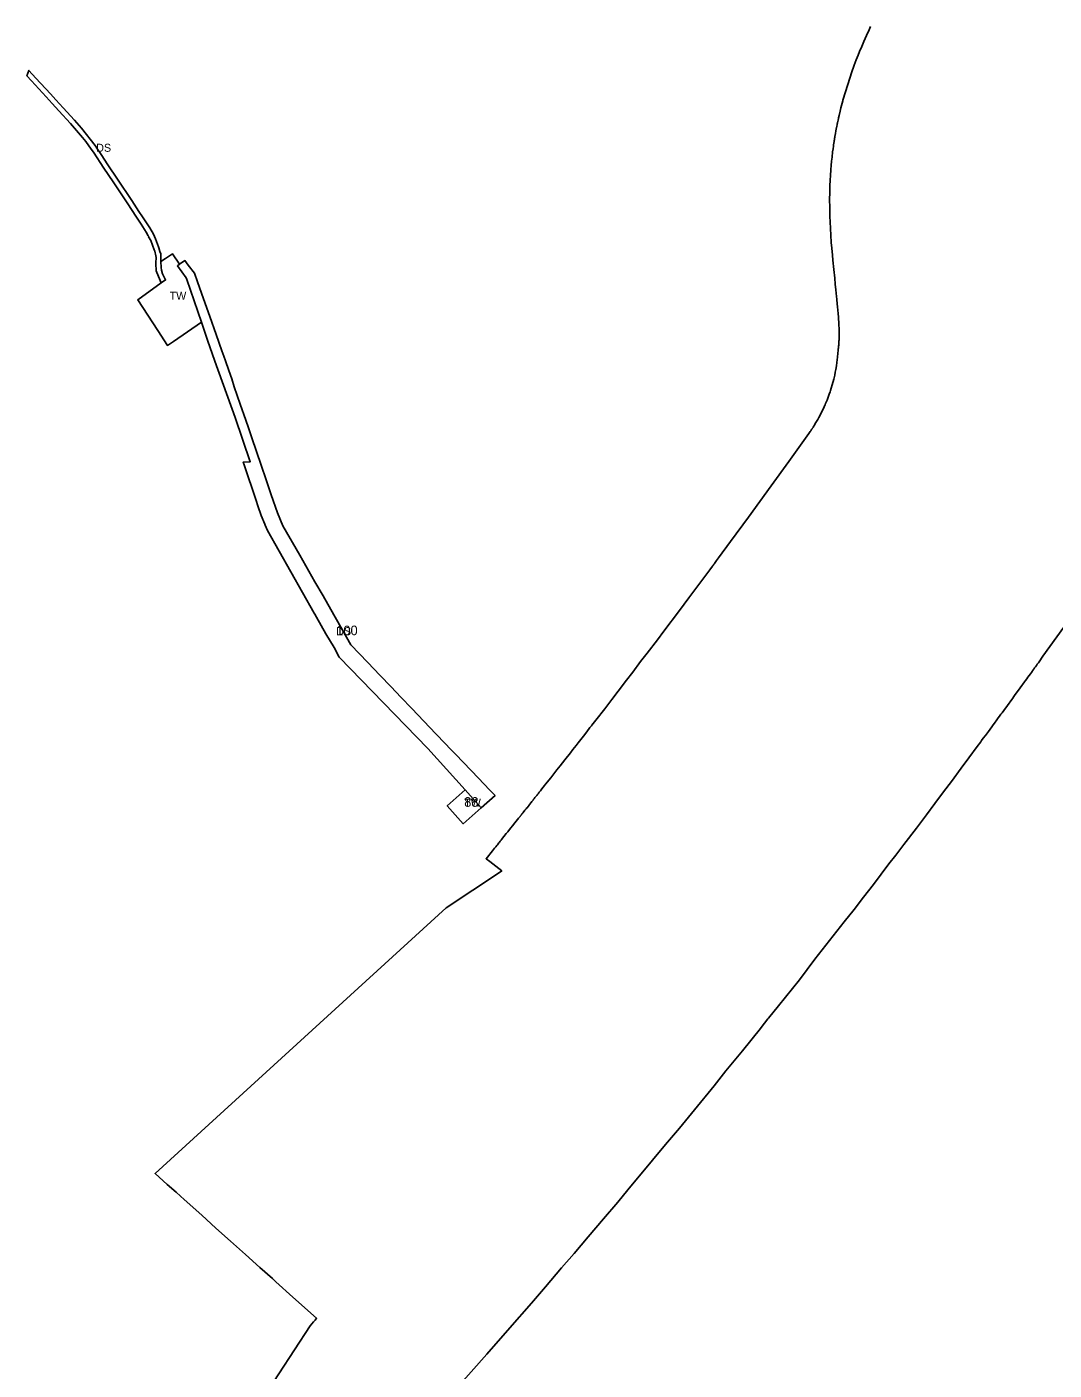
# Model space of a CAD drawing. Extents: x -537034 to -534353, y -1176562 to -1173176.
# Drawn here: x -536954 to -536312, y -1175264 to -1174424 of the extents above; entities that cross this region are included whole.
import ezdxf

# ---------------------------------------------------------------- set-up
doc = ezdxf.new("R2010")
doc.units = 0
for name, color, linetype in [('90320013', 7, 'Continuous'), ('90320023', 7, 'Continuous'), ('90390013', 7, 'Continuous'), ('90390023', 7, 'Continuous'), ('ID_navrh', 7, 'Continuous')]:
    doc.layers.add(name, color=color, linetype=linetype)

msp = doc.modelspace()

# ---------------------------------------------------------------- linework, layer by layer
at = {"layer": '90320013'}
msp.add_lwpolyline([(-536870.05, -1174584.29), (-536872.92, -1174577.74), (-536873.2, -1174576.81), (-536873.34, -1174575.78), (-536873.42, -1174573.04), (-536873.46, -1174571.78), (-536873.35, -1174568.3), (-536873.45, -1174567.27), (-536874.18, -1174564.4), (-536874.53, -1174563.49), (-536876.7, -1174557.85), (-536877.98, -1174555.36), (-536877.9, -1174555.32), (-536878.2, -1174554.93), (-536879.44, -1174552.52), (-536881.6, -1174549.14), (-536882.66, -1174547.54), (-536885.49, -1174543.27), (-536891.43, -1174534.31), (-536900.14, -1174521.16), (-536905.87, -1174512.49), (-536912.46, -1174502.53), (-536913.78, -1174500.58), (-536917.26, -1174495.97), (-536919.35, -1174493.41), (-536922.97, -1174488.98), (-536926.87, -1174484.67), (-536934.08, -1174476.7), (-536938.2, -1174472.15), (-536941.93, -1174468.07), (-536951.21, -1174457.91), (-536954.05, -1174454.82), (-536952.79, -1174451.48), (-536948.39, -1174456.27), (-536939.32, -1174466.18), (-536935.9, -1174469.92), (-536931.44, -1174474.85), (-536924.37, -1174482.66), (-536919.98, -1174487.52), (-536916.77, -1174491.47), (-536914.44, -1174494.34), (-536911.37, -1174498.46), (-536909.91, -1174500.61), (-536907.65, -1174504.01), (-536903.38, -1174510.45), (-536897.46, -1174519.36), (-536888.56, -1174532.8), (-536884.01, -1174539.67), (-536881.81, -1174543), (-536879.7, -1174546.18), (-536877.33, -1174549.77), (-536875, -1174553.88), (-536873.72, -1174556.72), (-536871.77, -1174561.68), (-536871.52, -1174562.3), (-536870.89, -1174564.58), (-536870.45, -1174566.17), (-536870.3, -1174570.06), (-536870.29, -1174570.93), (-536870.24, -1174574.67), (-536870.03, -1174576.27), (-536869.22, -1174578.49), (-536867.36, -1174582.37)], close=True, dxfattribs=at)
at = {"layer": '90320023'}
for points in [[(-536816.28, -1175295.99), (-536776.99, -1175235.99), (-536774.98, -1175233.56), (-536774.02, -1175232.4), (-536773.06, -1175231.25), (-536787.79, -1175218.03), (-536798.52, -1175208.4), (-536800.66, -1175206.48), (-536808.46, -1175199.48), (-536817.5, -1175191.37), (-536823.12, -1175186.33), (-536826.81, -1175183.01), (-536835.9, -1175174.86), (-536844.83, -1175166.84), (-536855.78, -1175157.03), (-536858.01, -1175155.03), (-536860.83, -1175152.5), (-536866.33, -1175147.56), (-536873.93, -1175140.73), (-536692.18, -1174974.82), (-536658.72, -1174952.6), (-536657.33, -1174951.7), (-536664.85, -1174945.87), (-536667.13, -1174944.05), (-536663.21, -1174939.22), (-536661.92, -1174937.56), (-536661.13, -1174936.6), (-536660.5, -1174935.81), (-536660.09, -1174935.3), (-536659.66, -1174934.77), (-536659.18, -1174934.18), (-536658.84, -1174933.75), (-536658.33, -1174933.11), (-536657.79, -1174932.45), (-536657.46, -1174932.04), (-536656.02, -1174930.25), (-536654.54, -1174928.39), (-536653.63, -1174927.29), (-536652.46, -1174925.78), (-536651.59, -1174924.68), (-536650.69, -1174923.6), (-536649.1, -1174921.6), (-536647.46, -1174919.54), (-536647.36, -1174919.42), (-536646.89, -1174918.83), (-536646.5, -1174918.35), (-536646.16, -1174917.92), (-536645.95, -1174917.66), (-536645.77, -1174917.42), (-536645.6, -1174917.21), (-536645.28, -1174916.82), (-536645.18, -1174916.69), (-536645.08, -1174916.56), (-536645, -1174916.46), (-536644.93, -1174916.38), (-536644.87, -1174916.3), (-536644.8, -1174916.21), (-536644.72, -1174916.11), (-536644.65, -1174916.03), (-536644.56, -1174915.91), (-536644.47, -1174915.8), (-536644.39, -1174915.7), (-536644.3, -1174915.59), (-536644.25, -1174915.52), (-536644.21, -1174915.47), (-536644.15, -1174915.4), (-536644.09, -1174915.33), (-536644.07, -1174915.29), (-536642.86, -1174913.78), (-536642.19, -1174912.94), (-536641.63, -1174912.24), (-536641.59, -1174912.18), (-536640.3, -1174910.57), (-536639.98, -1174910.16), (-536639.78, -1174909.91), (-536639.26, -1174909.25), (-536638.99, -1174908.91), (-536638.53, -1174908.33), (-536638.16, -1174907.86), (-536637.78, -1174907.39), (-536637.74, -1174907.34), (-536637.68, -1174907.27), (-536637.64, -1174907.22), (-536637.61, -1174907.17), (-536637.58, -1174907.13), (-536637.54, -1174907.09), (-536637.46, -1174906.99), (-536637.44, -1174906.96), (-536637.41, -1174906.92), (-536637.38, -1174906.89), (-536637.36, -1174906.86), (-536637.33, -1174906.82), (-536637.3, -1174906.79), (-536637.28, -1174906.75), (-536637.26, -1174906.73), (-536637.16, -1174906.61), (-536637.08, -1174906.5), (-536636.98, -1174906.38), (-536636.87, -1174906.25), (-536636.61, -1174905.91), (-536636.43, -1174905.68), (-536636.22, -1174905.42), (-536636.05, -1174905.2), (-536635.67, -1174904.73), (-536635.46, -1174904.47), (-536635.19, -1174904.12), (-536634.89, -1174903.74), (-536634.7, -1174903.51), (-536634.45, -1174903.19), (-536634.25, -1174902.94), (-536633.94, -1174902.54), (-536633.76, -1174902.32), (-536633.61, -1174902.14), (-536633.5, -1174901.99), (-536633.36, -1174901.81), (-536633.19, -1174901.6), (-536632.24, -1174900.39), (-536631.48, -1174899.43), (-536630.64, -1174898.39), (-536629.96, -1174897.51), (-536626.77, -1174893.47), (-536625.41, -1174891.77), (-536624.22, -1174890.21), (-536622.94, -1174888.63), (-536621.83, -1174887.2), (-536620.94, -1174886.06), (-536617.99, -1174882.2), (-536614.51, -1174877.99), (-536612.89, -1174875.89), (-536610.91, -1174873.26), (-536609.59, -1174871.58), (-536608.06, -1174869.62), (-536606.38, -1174867.43), (-536604.86, -1174865.53), (-536603.85, -1174864.22), (-536602.78, -1174862.8), (-536602.25, -1174862.13), (-536601.9, -1174861.7), (-536601.62, -1174861.35), (-536601.37, -1174861.02), (-536601.09, -1174860.66), (-536598.59, -1174857.48), (-536593, -1174850.36), (-536588.63, -1174844.54), (-536584.67, -1174839.44), (-536579.41, -1174832.4), (-536575.45, -1174827.55), (-536570.59, -1174820.91), (-536566.46, -1174815.57), (-536560.15, -1174807.24), (-536556.11, -1174801.9), (-536546.4, -1174789.03), (-536540.49, -1174781.02), (-536527.39, -1174763.63), (-536525.68, -1174761.21), (-536525.56, -1174761.05), (-536525.44, -1174760.88), (-536525.37, -1174760.79), (-536525.32, -1174760.72), (-536525.29, -1174760.69), (-536525.22, -1174760.59), (-536525.2, -1174760.56), (-536525.17, -1174760.53), (-536525.14, -1174760.49), (-536525.12, -1174760.45), (-536525.1, -1174760.43), (-536525.09, -1174760.41), (-536525.06, -1174760.38), (-536525.03, -1174760.34), (-536524.99, -1174760.27), (-536524.96, -1174760.24), (-536524.95, -1174760.23), (-536524.93, -1174760.2), (-536524.9, -1174760.17), (-536524.89, -1174760.15), (-536524.88, -1174760.14), (-536524.87, -1174760.12), (-536524.87, -1174760.11), (-536524.86, -1174760.11), (-536524.86, -1174760.1), (-536524.85, -1174760.09), (-536524.84, -1174760.08), (-536524.83, -1174760.07), (-536524.83, -1174760.06), (-536524.82, -1174760.06), (-536524.82, -1174760.05), (-536524.81, -1174760.04), (-536524.78, -1174760), (-536524.74, -1174759.94), (-536524.56, -1174759.7), (-536524.44, -1174759.54), (-536523.15, -1174757.8), (-536521.87, -1174756.07), (-536514.37, -1174745.87), (-536503.23, -1174730.7), (-536489.05, -1174710.98), (-536478.01, -1174695.81), (-536471.74, -1174687.11), (-536465.57, -1174678.46), (-536464.62, -1174677.1), (-536464.52, -1174676.95), (-536464.35, -1174676.7), (-536463.75, -1174675.8), (-536463.63, -1174675.62), (-536463.59, -1174675.57), (-536463.51, -1174675.44), (-536463.5, -1174675.42), (-536463.47, -1174675.39), (-536463.37, -1174675.23), (-536462.9, -1174674.51), (-536462.79, -1174674.34), (-536461.84, -1174672.83), (-536461.7, -1174672.59), (-536461.07, -1174671.55), (-536459.91, -1174669.56), (-536459.2, -1174668.27), (-536457.41, -1174664.84), (-536455.91, -1174661.68), (-536455.65, -1174661.05), (-536455.33, -1174660.34), (-536455.01, -1174659.61), (-536454.7, -1174658.86), (-536454.33, -1174657.95), (-536454.16, -1174657.54), (-536453.91, -1174656.9), (-536453.67, -1174656.3), (-536452.72, -1174653.7), (-536452.21, -1174652.22), (-536451.93, -1174651.39), (-536451.52, -1174650.08), (-536450.88, -1174647.95), (-536449.92, -1174644.38), (-536449.34, -1174641.85), (-536448.99, -1174640.13), (-536448.64, -1174638.38), (-536448.26, -1174636.09), (-536447.97, -1174634.02), (-536447.54, -1174630.65), (-536447.32, -1174628.16), (-536447.22, -1174626.58), (-536447.15, -1174625.52), (-536447.07, -1174624.96), (-536447.04, -1174624.72), (-536446.99, -1174624.33), (-536446.98, -1174624.28), (-536446.98, -1174624.26), (-536446.98, -1174624.21), (-536446.97, -1174624.17), (-536446.97, -1174624.14), (-536446.96, -1174624.12), (-536446.96, -1174624.11), (-536446.96, -1174624.08), (-536446.96, -1174624.07), (-536446.96, -1174624.06), (-536446.96, -1174624.05), (-536446.95, -1174624.04), (-536446.95, -1174624.03), (-536446.95, -1174624.02), (-536446.95, -1174624.01), (-536446.95, -1174624), (-536446.95, -1174623.99), (-536446.95, -1174623.98), (-536446.94, -1174623.94), (-536446.94, -1174623.91), (-536446.93, -1174623.79), (-536446.92, -1174623.71), (-536446.85, -1174623.08), (-536446.83, -1174622.89), (-536446.81, -1174622.59), (-536446.78, -1174622.29), (-536446.77, -1174622.08), (-536446.75, -1174621.87), (-536446.74, -1174621.65), (-536446.71, -1174621.32), (-536446.69, -1174620.98), (-536446.67, -1174620.5), (-536446.65, -1174620.02), (-536446.63, -1174619.64), (-536446.62, -1174619.25), (-536446.6, -1174618.72), (-536446.6, -1174618.45), (-536446.59, -1174618.18), (-536446.58, -1174617.76), (-536446.58, -1174617.47), (-536446.57, -1174615.98), (-536446.59, -1174614.72), (-536446.61, -1174613.55), (-536446.65, -1174612.34), (-536446.69, -1174611.08), (-536446.75, -1174609.77), (-536446.83, -1174608.4), (-536446.9, -1174607.24), (-536447.01, -1174605.57), (-536447.17, -1174603.39), (-536447.34, -1174601.34), (-536447.53, -1174599.2), (-536447.71, -1174597.24), (-536447.96, -1174594.69), (-536448.17, -1174592.58), (-536448.34, -1174590.95), (-536448.61, -1174588.44), (-536448.76, -1174587.01), (-536448.98, -1174584.97), (-536449.37, -1174581.34), (-536449.94, -1174575.9), (-536450.52, -1174570.12), (-536450.82, -1174566.91), (-536451.2, -1174562.49), (-536451.47, -1174559.05), (-536451.8, -1174554.37), (-536452.04, -1174550.3), (-536452.23, -1174546.1), (-536452.35, -1174542.66), (-536452.48, -1174536.44), (-536452.5, -1174532.78), (-536452.43, -1174527.15), (-536452.33, -1174523.79), (-536452.16, -1174519.88), (-536452.02, -1174517.4), (-536451.75, -1174513.36), (-536451.53, -1174510.81), (-536451.29, -1174508.22), (-536451.02, -1174505.61), (-536450.65, -1174502.44), (-536450.38, -1174500.38), (-536450.16, -1174498.73), (-536450.06, -1174498.03), (-536449.9, -1174496.98), (-536449.75, -1174495.96), (-536449.63, -1174495.19), (-536449.58, -1174494.88), (-536449.54, -1174494.59), (-536449.48, -1174494.26), (-536449.44, -1174493.97), (-536449.4, -1174493.77), (-536449.38, -1174493.66), (-536449.37, -1174493.59), (-536449.36, -1174493.51), (-536449.35, -1174493.46), (-536449.35, -1174493.45), (-536449.34, -1174493.41), (-536449.34, -1174493.4), (-536449.34, -1174493.39), (-536449.34, -1174493.38), (-536449.34, -1174493.37), (-536449.33, -1174493.36), (-536449.33, -1174493.35), (-536449.33, -1174493.34), (-536449.32, -1174493.29), (-536449.32, -1174493.28), (-536449.32, -1174493.25), (-536449.31, -1174493.22), (-536449.3, -1174493.17), (-536449.3, -1174493.16), (-536449.3, -1174493.15), (-536449.3, -1174493.13), (-536449.29, -1174493.12), (-536449.29, -1174493.11), (-536449.29, -1174493.1), (-536449.29, -1174493.09), (-536449.29, -1174493.07), (-536449.28, -1174493.06), (-536449.27, -1174492.95), (-536449.26, -1174492.94), (-536449.26, -1174492.93), (-536449.26, -1174492.91), (-536449.25, -1174492.87), (-536449.25, -1174492.83), (-536448.92, -1174490.92), (-536448.6, -1174489.21), (-536448.4, -1174488.1), (-536448.06, -1174486.4), (-536447.9, -1174485.53), (-536447.78, -1174484.97), (-536447.76, -1174484.86), (-536447.74, -1174484.78), (-536447.74, -1174484.77), (-536447.73, -1174484.75), (-536447.73, -1174484.74), (-536447.73, -1174484.73), (-536447.72, -1174484.7), (-536447.71, -1174484.65), (-536447.7, -1174484.59), (-536447.68, -1174484.5), (-536447.66, -1174484.39), (-536447.65, -1174484.33), (-536447.63, -1174484.24), (-536447.62, -1174484.19), (-536447.6, -1174484.11), (-536447.59, -1174484.05), (-536447.57, -1174483.97), (-536447.56, -1174483.92), (-536447.54, -1174483.83), (-536447.53, -1174483.76), (-536447.5, -1174483.64), (-536447.48, -1174483.54), (-536447.44, -1174483.34), (-536447.27, -1174482.55), (-536447.06, -1174481.6), (-536446.96, -1174481.14), (-536446.6, -1174479.57), (-536445.99, -1174476.98), (-536445.48, -1174474.94), (-536445.09, -1174473.42), (-536444.7, -1174471.91), (-536444.29, -1174470.42), (-536444.22, -1174470.15), (-536439.72, -1174455.61), (-536438.86, -1174453.07), (-536437.13, -1174448.29), (-536435.86, -1174444.91), (-536434.73, -1174442.03), (-536433.76, -1174439.61), (-536432.46, -1174436.46), (-536431.16, -1174433.39), (-536429.52, -1174429.63), (-536427.91, -1174426.04), (-536426.96, -1174423.95)], [(-536306.21, -1174799.45), (-536319.22, -1174817.54), (-536321.7, -1174821.05), (-536322.11, -1174821.6), (-536322.8, -1174822.56), (-536323.37, -1174823.37), (-536323.96, -1174824.17), (-536324.46, -1174824.88), (-536324.93, -1174825.53), (-536325.38, -1174826.13), (-536326.49, -1174827.68), (-536327.04, -1174828.44), (-536327.95, -1174829.68), (-536328.7, -1174830.71), (-536329.35, -1174831.62), (-536330.14, -1174832.7), (-536330.7, -1174833.51), (-536333.49, -1174837.29), (-536335.68, -1174840.44), (-536336.55, -1174841.54), (-536337.44, -1174842.77), (-536338.16, -1174843.75), (-536338.79, -1174844.63), (-536341.42, -1174848.25), (-536342.53, -1174849.75), (-536343.34, -1174850.86), (-536343.77, -1174851.45), (-536344.78, -1174852.84), (-536345.53, -1174853.83), (-536346.36, -1174854.99), (-536347.15, -1174856.04), (-536347.98, -1174857.21), (-536349.51, -1174859.28), (-536350.3, -1174860.39), (-536351.21, -1174861.58), (-536353.3, -1174864.49), (-536355.24, -1174867), (-536356.53, -1174868.82), (-536357.54, -1174870.19), (-536358.05, -1174870.93), (-536358.91, -1174872.07), (-536359.54, -1174872.92), (-536360.38, -1174874.04), (-536365.51, -1174880.99), (-536370.44, -1174887.54), (-536376.43, -1174895.8), (-536381.45, -1174902.35), (-536386.87, -1174909.63), (-536391.96, -1174916.59), (-536398.28, -1174925), (-536406.2, -1174935.2), (-536411.22, -1174941.83), (-536415.59, -1174947.33), (-536425.14, -1174960.28), (-536431.45, -1174968.05), (-536437.27, -1174975.81), (-536443.42, -1174983.42), (-536450.22, -1174992.32), (-536461.87, -1175006.88), (-536471.26, -1175019.83), (-536484.52, -1175036.01), (-536490.68, -1175043.69), (-536491.08, -1175044.18), (-536495.33, -1175049.61), (-536495.34, -1175049.61), (-536495.77, -1175050.17), (-536507.02, -1175064.09), (-536517.37, -1175076.71), (-536524.65, -1175086.09), (-536536.95, -1175100.98), (-536546.34, -1175112.47), (-536555, -1175122.74), (-536563.09, -1175132.53), (-536578.54, -1175151.06), (-536584.77, -1175158.59), (-536593.75, -1175169.19), (-536603.3, -1175180.35), (-536612.2, -1175190.87), (-536619.97, -1175199.77), (-536630.12, -1175211.7), (-536633.72, -1175215.87), (-536638.82, -1175221.78), (-536652.37, -1175237.23), (-536666.61, -1175253.57), (-536687.97, -1175277.68)]]:
    msp.add_lwpolyline(points, dxfattribs=at)
msp.add_lwpolyline([(-536858.6, -1174572.62), (-536855.32, -1174570.31), (-536853.23, -1174573.07), (-536849.37, -1174578.18), (-536847.43, -1174583.64), (-536843.67, -1174594.24), (-536839.8, -1174605.15), (-536835.8, -1174616.43), (-536832.15, -1174626.71), (-536830.96, -1174630.05), (-536829.94, -1174633.05), (-536827.9, -1174639.03), (-536826.1, -1174644.29), (-536824.45, -1174649.13), (-536822.6, -1174654.56), (-536820.76, -1174659.94), (-536817.34, -1174669.94), (-536815.69, -1174674.78), (-536813.53, -1174681.1), (-536807.68, -1174698.23), (-536804.55, -1174707.41), (-536801.4, -1174716.65), (-536797.54, -1174727.95), (-536794.07, -1174735.98), (-536783.59, -1174754.35), (-536774.06, -1174771.04), (-536769, -1174779.9), (-536764.23, -1174788.25), (-536754.29, -1174805.66), (-536751.55, -1174810.45), (-536740.95, -1174821.53), (-536733.51, -1174829.3), (-536726.48, -1174836.66), (-536720.34, -1174843.08), (-536713.63, -1174850.1), (-536698.47, -1174865.96), (-536692.66, -1174872.04), (-536689.34, -1174875.51), (-536685.97, -1174879.04), (-536671.86, -1174893.79), (-536664.96, -1174901.01), (-536661.56, -1174904.56), (-536670.24, -1174912.25), (-536680.18, -1174901.02), (-536703.62, -1174875.13), (-536758.86, -1174818.06), (-536762.07, -1174812.08), (-536767.18, -1174803.45), (-536773.05, -1174793.18), (-536774.18, -1174791.2), (-536774.51, -1174790.62), (-536803.79, -1174738.89), (-536805.19, -1174735.68), (-536805.44, -1174735.08), (-536807.71, -1174729.63), (-536809.68, -1174723.6), (-536810.85, -1174720.21), (-536818.3, -1174697.92), (-536818.87, -1174696.2), (-536814.54, -1174695.99), (-536824.01, -1174668.43), (-536836.56, -1174633.08), (-536841.1, -1174619.95), (-536844.98, -1174608.71), (-536854.16, -1174582.13), (-536854.6, -1174581.18), (-536859.98, -1174573.6)], close=True, dxfattribs=at)
at = {"layer": '90390013'}
msp.add_lwpolyline([(-536858.6, -1174572.62), (-536859.98, -1174573.6), (-536854.6, -1174581.18), (-536854.16, -1174582.13), (-536844.98, -1174608.71), (-536862.53, -1174620.78), (-536866.23, -1174623.31), (-536872.24, -1174614.03), (-536878.46, -1174604.43), (-536884.74, -1174594.73), (-536870.05, -1174584.29), (-536867.36, -1174582.37), (-536869.22, -1174578.49), (-536870.03, -1174576.27), (-536870.24, -1174574.67), (-536870.29, -1174570.93), (-536867.52, -1174569.06), (-536863.08, -1174566.08)], close=True, dxfattribs=at)
at = {"layer": '90390023'}
msp.add_lwpolyline([(-536680.18, -1174901.02), (-536670.24, -1174912.25), (-536681.47, -1174922.19), (-536691.41, -1174910.96)], close=True, dxfattribs=at)

# ---------------------------------------------------------------- texts
at = {"layer": '90320013'}
msp.add_text('DS', height=5, rotation=360, dxfattribs=at).set_placement((-536910.71, -1174502.31))
at = {"layer": '90320023'}
msp.add_text('DS', height=5, rotation=360, dxfattribs=at).set_placement((-536760.77, -1174804.41))
at = {"layer": '90390013'}
msp.add_text('TW', height=5, rotation=360, dxfattribs=at).set_placement((-536864.86, -1174594.82))
at = {"layer": '90390023'}
msp.add_text('TW', height=5, rotation=0, dxfattribs=at).set_placement((-536680.82, -1174911.61))
at = {"layer": 'ID_navrh'}
for s, rotation, p in [('100', 360, (-536760.77, -1174804.41)), ('88', 0, (-536680.82, -1174911.61))]:
    msp.add_text(s, height=6, rotation=rotation, dxfattribs=at).set_placement(p)

doc.saveas('drawing.dxf')
